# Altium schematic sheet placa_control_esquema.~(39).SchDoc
size A4
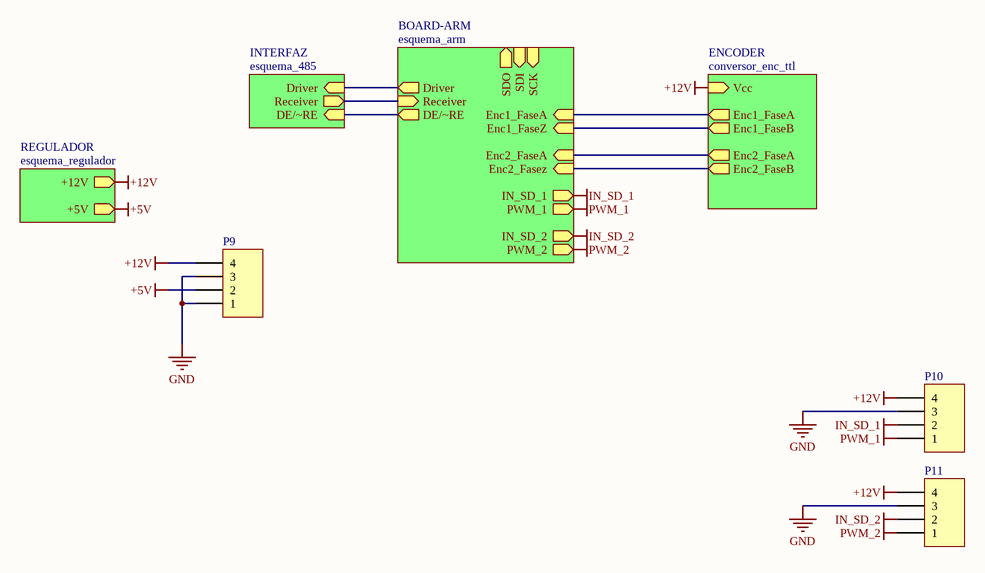
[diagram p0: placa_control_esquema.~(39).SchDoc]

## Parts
P9  Header 4  [HDR1X5]  (value not drawn)
P10  Header 4  [HDR1X5]  (value not drawn)
P11  Header 4  [HDR1X5]  (value not drawn)

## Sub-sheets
BOARD-ARM = esquema_arm: SDI (in), SDO (out), SCK (in), Enc1_FaseA (in), Enc1_FaseZ (in), Enc2_FaseA (in), Enc2_Fasez (in), DE/~RE (out), Receiver (in), Driver (out), PWM_1 (out), PWM_2 (out), IN_SD_2 (out), IN_SD_1 (out)
ENCODER = conversor_enc_ttl: Enc1_FaseA (out), Enc1_FaseB (out), Enc2_FaseA (out), Enc2_FaseB (out), Vcc (in)
INTERFAZ = esquema_485: Driver (in), Receiver (out), DE/~RE (in)
REGULADOR = esquema_regulador: +12V (out), +5V (out)

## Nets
+5V: P9.2 ; sheet REGULADOR/+5V
+12V: P9.4 P10.4 P11.4 ; sheet REGULADOR/+12V, sheet ENCODER/Vcc
GND: P9.1 P9.3 P10.3 P11.3
IN_SD_1: P10.2 ; sheet BOARD-ARM/IN_SD_1
IN_SD_2: P11.2 ; sheet BOARD-ARM/IN_SD_2
PWM_1: P10.1 ; sheet BOARD-ARM/PWM_1
PWM_2: P11.1 ; sheet BOARD-ARM/PWM_2
(unnamed): sheet INTERFAZ/Driver, sheet BOARD-ARM/Driver
(unnamed): sheet INTERFAZ/Receiver, sheet BOARD-ARM/Receiver  [a separate net that carries the same name]
(unnamed): sheet INTERFAZ/DE/~RE, sheet BOARD-ARM/DE/~RE  [a separate net that carries the same name]
(unnamed): sheet BOARD-ARM/Enc1_FaseA, sheet ENCODER/Enc1_FaseA  [a separate net that carries the same name]
(unnamed): sheet BOARD-ARM/Enc1_FaseZ, sheet ENCODER/Enc1_FaseB  [a separate net that carries the same name]
(unnamed): sheet BOARD-ARM/Enc2_FaseA, sheet ENCODER/Enc2_FaseA  [a separate net that carries the same name]
(unnamed): sheet BOARD-ARM/Enc2_Fasez, sheet ENCODER/Enc2_FaseB  [a separate net that carries the same name]

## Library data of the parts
P9-P11 = Header 4: Header, 4-Pin; value: hdr1x5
